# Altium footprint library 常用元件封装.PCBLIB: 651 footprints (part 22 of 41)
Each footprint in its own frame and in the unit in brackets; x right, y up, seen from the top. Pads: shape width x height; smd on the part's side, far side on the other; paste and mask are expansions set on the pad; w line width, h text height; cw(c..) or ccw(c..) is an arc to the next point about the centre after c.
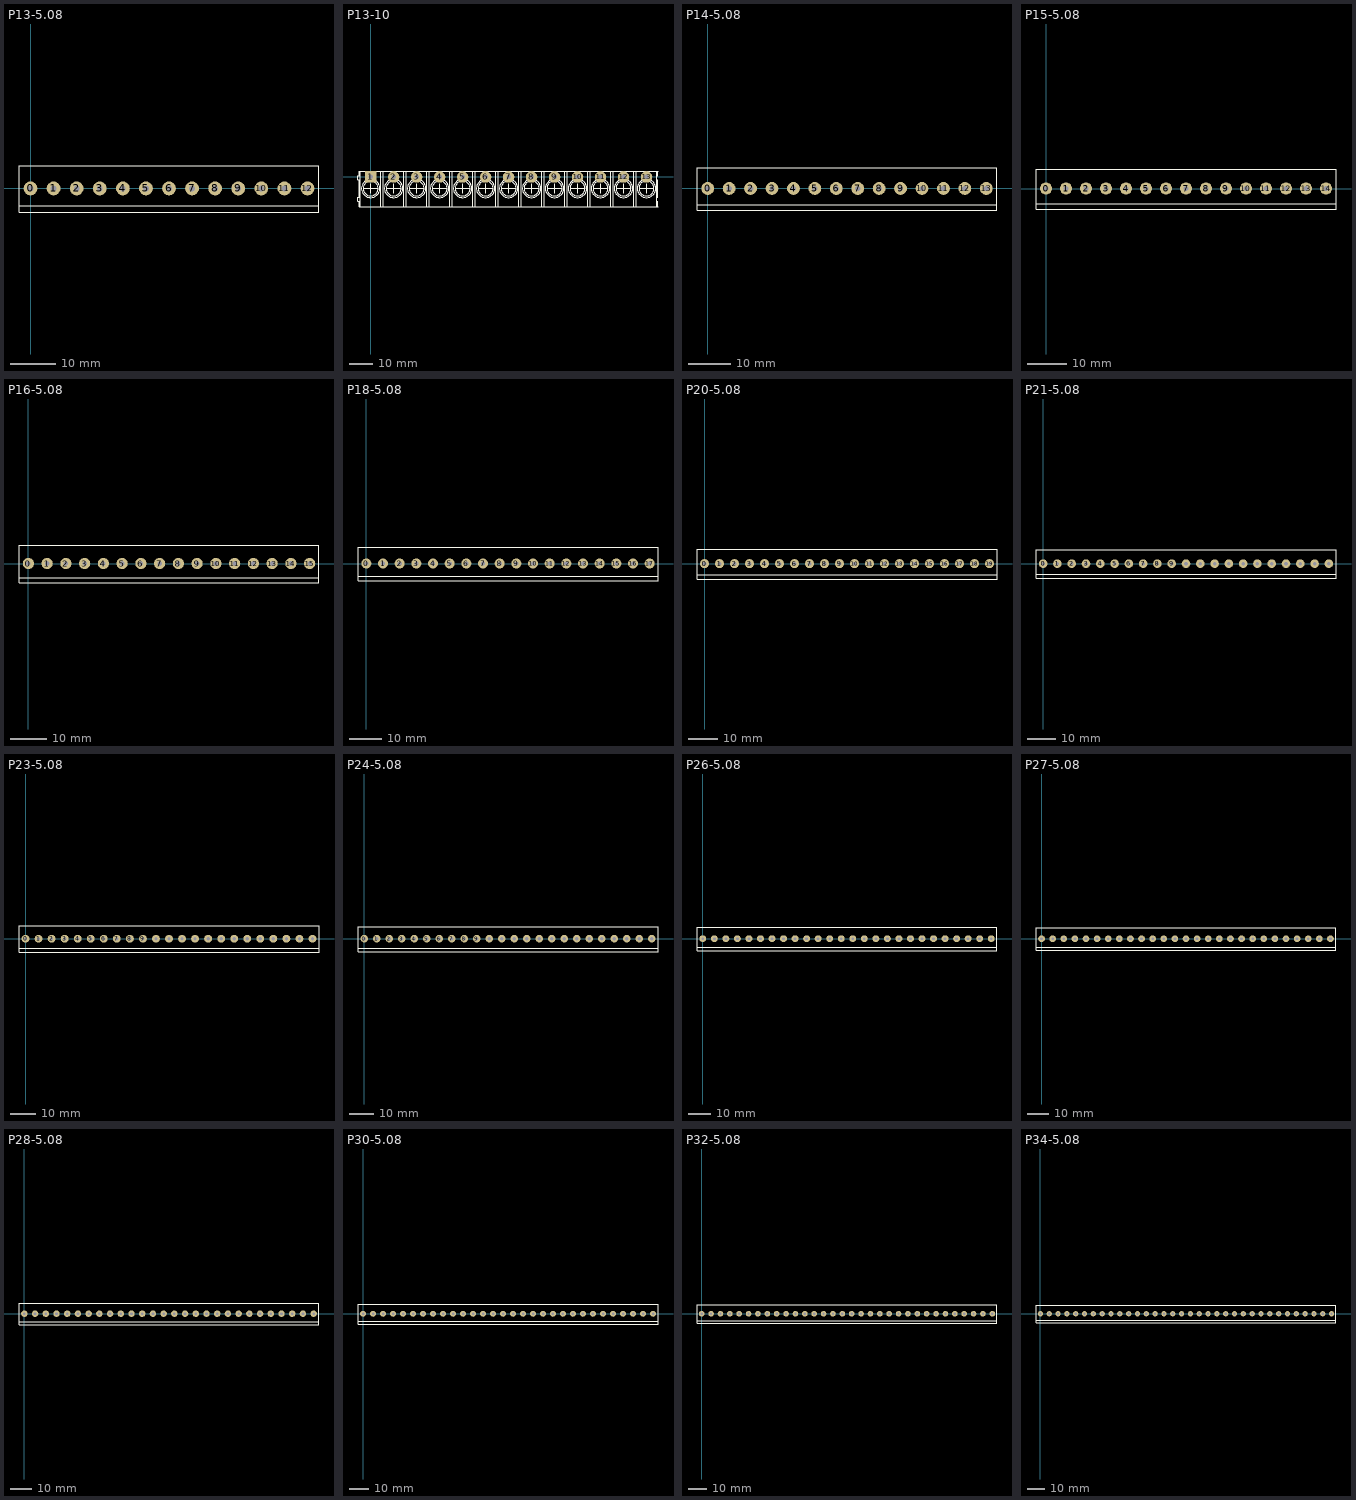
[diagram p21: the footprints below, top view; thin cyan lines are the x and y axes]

## P13-5.08 [mil]
height 543.31
pads (13):
  round 120 hole 50: 0(0,0) 1(200,0) 2(400,0) 3(600,0) 4(800,0) 5(1000,0) 6(1200,0) 7(1400,0) 8(1600,0) 9(1800,0) 10(2000,0) 11(2200,0) 12(2400,0)
TopOverlay:
  lines w6.69: -100,-150 2500,-150 ; -100,-205 2500,-205 2500,195 -100,195 -100,-205

## P13-10 [mm]
pads (13):
  rect 5x5 hole 2: 1(0,0)
  round 5 hole 2: 2(10,0) 3(20,0) 4(30,0) 5(40,0) 6(50,0) 7(60,0) 8(70,0) 9(80,0) 10(90,0) 11(100,0) 12(110,0) 13(120,0)
TopOverlay:
  circle w0.254: c0,-5 r3.26
  circle w0.254: c0,-5 r4
  circle w0.254: c10,-5 r3.26
  circle w0.254: c10,-5 r4
  circle w0.254: c20,-5 r3.26
  circle w0.254: c20,-5 r4
  circle w0.254: c30,-5 r3.26
  circle w0.254: c30,-5 r4
  circle w0.254: c40,-5 r3.26
  circle w0.254: c40,-5 r4
  circle w0.254: c50,-5 r3.26
  circle w0.254: c50,-5 r4
  circle w0.254: c60,-5 r3.26
  circle w0.254: c60,-5 r4
  circle w0.254: c70,-5 r3.26
  circle w0.254: c70,-5 r4
  circle w0.254: c80,-5 r3.26
  circle w0.254: c80,-5 r4
  circle w0.254: c90,-5 r3.26
  circle w0.254: c90,-5 r4
  circle w0.254: c100,-5 r3.26
  circle w0.254: c100,-5 r4
  circle w0.254: c110,-5 r3.26
  circle w0.254: c110,-5 r4
  circle w0.254: c120,-5 r3.26
  circle w0.254: c120,-5 r4
  lines w0.254: -4.5,-13 -4.5,2.5 ; -3.25,-5 3.25,-5 ; 0,-7 0,-3 ; 4.5,-13 4.5,2.5 ; 5.5,-13 5.5,2.5 ; 6.75,-5 13.25,-5 ; 10,-7 10,-3 ; 14.5,-13 14.5,2.5 ; 15.5,-13 15.5,2.5 ; 16.75,-5 23.25,-5 ; 20,-7 20,-3 ; 24.5,-13 24.5,2.5 ; 25.5,-13 25.5,2.5 ; 26.75,-5 33.25,-5 ; 30,-7 30,-3 ; 34.5,-13 34.5,2.5 ; 35.5,-13 35.5,2.5 ; 36.75,-5 43.25,-5 ; 40,-7 40,-3 ; 44.5,-13 44.5,2.5 ; 45.5,-13 45.5,2.5 ; 46.75,-5 53.25,-5 ; 50,-7 50,-3 ; 54.5,-13 54.5,2.5 ; 55.5,-13 55.5,2.5 ; 56.75,-5 63.25,-5 ; 60,-7 60,-3 ; 64.5,-13 64.5,2.5 ; 65.5,-13 65.5,2.5 ; 66.75,-5 73.25,-5 ; 70,-7 70,-3 ; 74.5,-13 74.5,2.5 ; 75.5,-13 75.5,2.5 ; 76.75,-5 83.25,-5 ; 80,-7 80,-3 ; 84.5,-13 84.5,2.5 ; 85.5,-13 85.5,2.5 ; 86.75,-5 93.25,-5 ; 90,-7 90,-3 ; 94.5,-13 94.5,2.5 ; 95.5,-13 95.5,2.5 ; 96.75,-5 103.25,-5 ; 100,-7 100,-3 ; 104.5,-13 104.5,2.5 ; 105.5,-13 105.5,2.5 ; 106.75,-5 113.25,-5 ; 110,-7 110,-3 ; 114.5,-13 114.5,2.5 ; 114.5,-10.5 114.5,-8.75 ; 114.5,-1.25 114.5,0.5 ; 115.5,-13 115.5,2.5 ; 116.75,-5 123.25,-5 ; 120,-7 120,-3 ; 124.5,-13 124.5,2.5 ; 125,-13 125,-10.5 124.5,-10.5 124.5,-8.75 125,-8.75 125,-1.25 124.5,-1.25 124.5,0.5 125,0.5 125,2.5 ; 125,-12.975 75,-13 35,-13 -5,-13 -5,-10.5 -5.5,-10.5 -5.5,-8.75 -5,-8.75 -5,-1.25 -5.5,-1.25 -5.5,0.5 -5,0.5 -5,2.5 35,2.5 75,2.5 125,2.475 ; 34.5,-10.5 34.5,-8.75 34.5,-10.5 ; 34.5,-1.25 34.5,0.5 34.5,-1.25 ; 74.5,-10.5 74.5,-8.75 74.5,-10.5 ; 74.5,-1.25 74.5,0.5 74.5,-1.25

## P14-5.08 [mil]
height 543.31
pads (14):
  round 120 hole 50: 0(0,0) 1(200,0) 2(400,0) 3(600,0) 4(800,0) 5(1000,0) 6(1200,0) 7(1400,0) 8(1600,0) 9(1800,0) 10(2000,0) 11(2200,0) 12(2400,0) 13(2600,0)
TopOverlay:
  lines w6.69: -100,-150 2700,-150 ; -100,-205 -100,195 2700,195 2700,-205 -100,-205

## P15-5.08 [mil]
height 543.31
pads (15):
  round 120 hole 50: 0(0,0) 1(200,0) 2(400,0) 3(600,0) 4(800,0) 5(1000,0) 6(1200,0) 7(1400,0) 8(1600,0) 9(1800,0) 10(2000,0) 11(2200,0) 12(2400,0) 13(2600,0) 14(2800,0)
TopOverlay:
  lines w6.69: -100,-150 2900,-150 ; -100,-205 -100,195 2900,195 2900,-205 -100,-205

## P16-5.08 [mil]
height 543.31
pads (16):
  round 120 hole 50: 0(0,0) 1(200,0) 2(400,0) 3(600,0) 4(800,0) 5(1000,0) 6(1200,0) 7(1400,0) 8(1600,0) 9(1800,0) 10(2000,0) 11(2200,0) 12(2400,0) 13(2600,0) 14(2800,0) 15(3000,0)
TopOverlay:
  lines w6.69: -100,-150 3100,-150 ; -100,-205 3100,-205 3100,195 -100,195 -100,-205

## P18-5.08 [mil]
height 543.31
pads (18):
  round 120 hole 50: 0(0,0) 1(200,0) 2(400,0) 3(600,0) 4(800,0) 5(1000,0) 6(1200,0) 7(1400,0) 8(1600,0) 9(1800,0) 10(2000,0) 11(2200,0) 12(2400,0) 13(2600,0) 14(2800,0) 15(3000,0) 16(3200,0) 17(3400,0)
TopOverlay:
  lines w6.69: -100,-150 3500,-150 ; -100,-205 3500,-205 3500,195 -100,195 -100,-205

## P20-5.08 [mil]
height 543.31
pads (20):
  round 120 hole 50: 0(0,0) 1(200,0) 2(400,0) 3(600,0) 4(800,0) 5(1000,0) 6(1200,0) 7(1400,0) 8(1600,0) 9(1800,0) 10(2000,0) 11(2200,0) 12(2400,0) 13(2600,0) 14(2800,0) 15(3000,0) 16(3200,0) 17(3400,0) 18(3600,0) 19(3800,0)
TopOverlay:
  lines w6.69: -100,-150 3900,-150 ; -100,-205 -100,195 3900,195 3900,-205 -100,-205

## P21-5.08 [mil]
height 543.31
pads (21):
  round 120 hole 50: 0(0,0) 1(200,0) 2(400,0) 3(600,0) 4(800,0) 5(1000,0) 6(1200,0) 7(1400,0) 8(1600,0) 9(1800,0) 10(2000,0) 11(2200,0) 12(2400,0) 13(2600,0) 14(2800,0) 15(3000,0) 16(3200,0) 17(3400,0) 18(3600,0) 19(3800,0) 20(4000,0)
TopOverlay:
  lines w6.69: -100,-150 4100,-150 ; -100,-205 4100,-205 4100,195 -100,195 -100,-205

## P23-5.08 [mil]
height 543.31
pads (23):
  round 120 hole 50: 0(0,0) 1(200,0) 2(400,0) 3(600,0) 4(800,0) 5(1000,0) 6(1200,0) 7(1400,0) 8(1600,0) 9(1800,0) 10(2000,0) 11(2200,0) 12(2400,0) 13(2600,0) 14(2800,0) 15(3000,0) 16(3200,0) 17(3400,0) 18(3600,0) 19(3800,0) 20(4000,0) 21(4200,0) 22(4400,0)
TopOverlay:
  lines w6.69: -100,-150 4500,-150 ; -100,-205 -100,195 4500,195 4500,-205 -100,-205

## P24-5.08 [mil]
height 543.31
pads (24):
  round 120 hole 50: 0(0,0) 1(200,0) 2(400,0) 3(600,0) 4(800,0) 5(1000,0) 6(1200,0) 7(1400,0) 8(1600,0) 9(1800,0) 10(2000,0) 11(2200,0) 12(2400,0) 13(2600,0) 14(2800,0) 15(3000,0) 16(3200,0) 17(3400,0) 18(3600,0) 19(3800,0) 20(4000,0) 21(4200,0) 22(4400,0) 23(4600,0)
TopOverlay:
  lines w6.69: -100,-150 4700,-150 ; -100,-205 4700,-205 4700,195 -100,195 -100,-205

## P26-5.08 [mil]
height 543.31
pads (26):
  round 120 hole 50: 0(0,0) 1(200,0) 2(400,0) 3(600,0) 4(800,0) 5(1000,0) 6(1200,0) 7(1400,0) 8(1600,0) 9(1800,0) 10(2000,0) 11(2200,0) 12(2400,0) 13(2600,0) 14(2800,0) 15(3000,0) 16(3200,0) 17(3400,0) 18(3600,0) 19(3800,0) 20(4000,0) 21(4200,0) 22(4400,0) 23(4600,0) 24(4800,0) 25(5000,0)
TopOverlay:
  lines w6.69: -100,-150 5100,-150 ; -100,-205 5100,-205 5100,195 -100,195 -100,-205

## P27-5.08 [mil]
height 543.31
pads (27):
  round 120 hole 50: 0(0,0) 1(200,0) 2(400,0) 3(600,0) 4(800,0) 5(1000,0) 6(1200,0) 7(1400,0) 8(1600,0) 9(1800,0) 10(2000,0) 11(2200,0) 12(2400,0) 13(2600,0) 14(2800,0) 15(3000,0) 16(3200,0) 17(3400,0) 18(3600,0) 19(3800,0) 20(4000,0) 21(4200,0) 22(4400,0) 23(4600,0) 24(4800,0) 25(5000,0) 26(5200,0)
TopOverlay:
  lines w6.69: -100,-150 5300,-150 ; -100,-205 5300,-205 5300,195 -100,195 -100,-205

## P28-5.08 [mil]
height 543.31
pads (28):
  round 120 hole 50: 0(0,0) 1(200,0) 2(400,0) 3(600,0) 4(800,0) 5(1000,0) 6(1200,0) 7(1400,0) 8(1600,0) 9(1800,0) 10(2000,0) 11(2200,0) 12(2400,0) 13(2600,0) 14(2800,0) 15(3000,0) 16(3200,0) 17(3400,0) 18(3600,0) 19(3800,0) 20(4000,0) 21(4200,0) 22(4400,0) 23(4600,0) 24(4800,0) 25(5000,0) 26(5200,0) 27(5400,0)
TopOverlay:
  lines w6.69: -100,-150 5500,-150 ; -100,-205 5500,-205 5500,195 -100,195 -100,-205

## P30-5.08 [mil]
height 543.31
pads (30):
  round 120 hole 50: 0(0,0) 1(200,0) 2(400,0) 3(600,0) 4(800,0) 5(1000,0) 6(1200,0) 7(1400,0) 8(1600,0) 9(1800,0) 10(2000,0) 11(2200,0) 12(2400,0) 13(2600,0) 14(2800,0) 15(3000,0) 16(3200,0) 17(3400,0) 18(3600,0) 19(3800,0) 20(4000,0) 21(4200,0) 22(4400,0) 23(4600,0) 24(4800,0) 25(5000,0) 26(5200,0) 27(5400,0) 28(5600,0) 29(5800,0)
TopOverlay:
  lines w6.69: -100,-150 5900,-150 ; -100,-205 5900,-205 5900,195 -100,195 -100,-205

## P32-5.08 [mil]
height 543.31
pads (32):
  round 120 hole 50: 0(0,0) 1(200,0) 2(400,0) 3(600,0) 4(800,0) 5(1000,0) 6(1200,0) 7(1400,0) 8(1600,0) 9(1800,0) 10(2000,0) 11(2200,0) 12(2400,0) 13(2600,0) 14(2800,0) 15(3000,0) 16(3200,0) 17(3400,0) 18(3600,0) 19(3800,0) 20(4000,0) 21(4200,0) 22(4400,0) 23(4600,0) 24(4800,0) 25(5000,0) 26(5200,0) 27(5400,0) 28(5600,0) 29(5800,0) 30(6000,0) 31(6200,0)
TopOverlay:
  lines w6.69: -100,-150 6300,-150 ; -100,-205 -100,195 6300,195 6300,-205 -100,-205

## P34-5.08 [mil]
height 543.31
pads (34):
  round 120 hole 50: 0(0,0) 1(200,0) 2(400,0) 3(600,0) 4(800,0) 5(1000,0) 6(1200,0) 7(1400,0) 8(1600,0) 9(1800,0) 10(2000,0) 11(2200,0) 12(2400,0) 13(2600,0) 14(2800,0) 15(3000,0) 16(3200,0) 17(3400,0) 18(3600,0) 19(3800,0) 20(4000,0) 21(4200,0) 22(4400,0) 23(4600,0) 24(4800,0) 25(5000,0) 26(5200,0) 27(5400,0) 28(5600,0) 29(5800,0) 30(6000,0) 31(6200,0) 32(6400,0) 33(6600,0)
TopOverlay:
  lines w6.69: -100,-150 6700,-150 ; -100,-205 -100,195 6700,195 6700,-205 -100,-205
